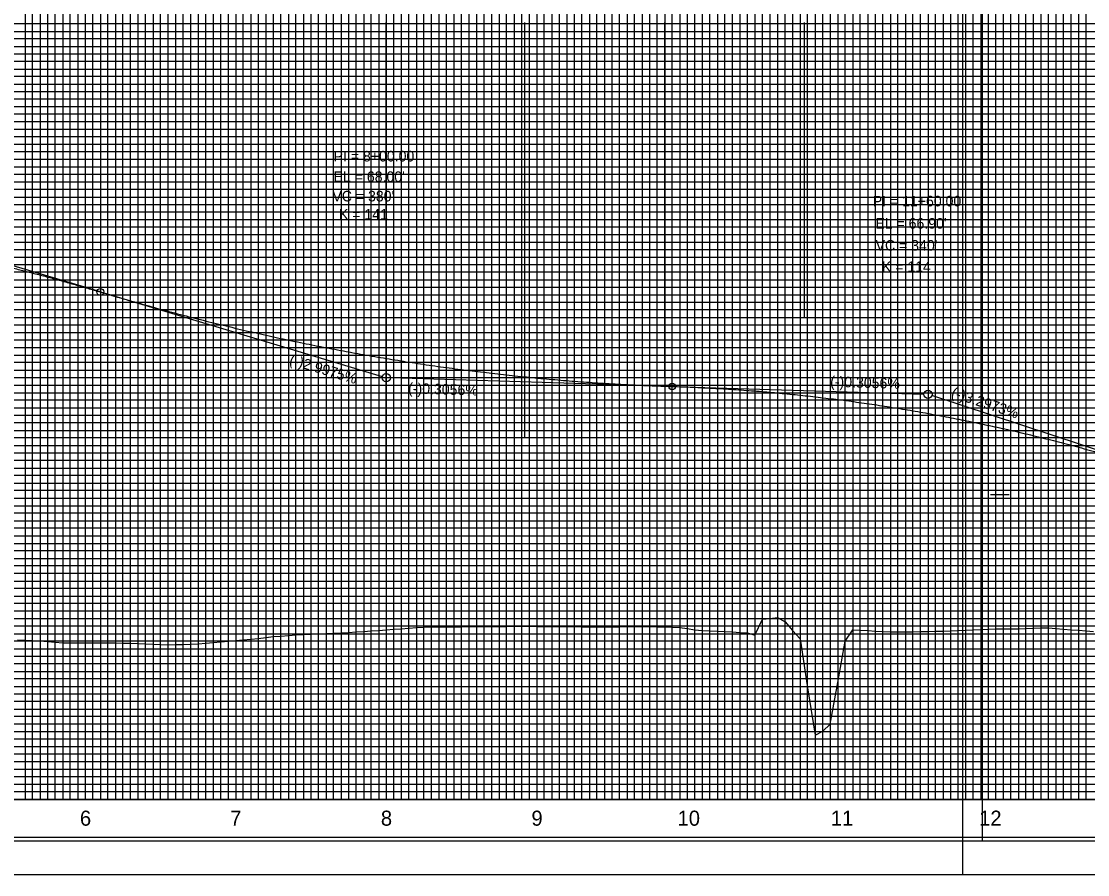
# Model space of a CAD drawing. Extents: x 2345490 to 2445302, y 465165 to 573888.
# Drawn here: x 2411453 to 2412161, y 502766 to 503333 of the extents above; entities that cross this region are included whole.
import ezdxf

# ---------------------------------------------------------------- set-up
doc = ezdxf.new("R2010")
doc.units = 0
for name, color, linetype in [('Old_Level_1', 7, 'Continuous'), ('Old_Level_18', 7, 'Continuous'), ('Old_Level_2', 7, 'Continuous'), ('Old_Level_41', 7, 'Continuous'), ('Old_Level_42', 7, 'Continuous'), ('Old_Level_43', 7, 'Continuous'), ('Old_Level_50', 7, 'Continuous'), ('Old_Level_51', 7, 'Continuous'), ('Old_Level_52', 7, 'Continuous'), ('Old_Level_63', 7, 'Continuous')]:
    doc.layers.add(name, color=color, linetype=linetype)

msp = doc.modelspace()

# ---------------------------------------------------------------- linework, layer by layer
at = {"layer": 'Old_Level_1'}
for points in [[(2411895.325, 502929.42025), (2411900.325, 502928.51975), (2411905.325, 502928.06175), (2411910.325, 502927.8235), (2411915.325, 502927.59575), (2411920.325, 502927.363), (2411925.325, 502927.125), (2411930.325, 502926.882), (2411935.325, 502926.634), (2411940.325, 502925.0755), (2411945.325, 502935.56225), (2411950.325, 502936.16175), (2411955.325, 502936.8355), (2411960.325, 502933.937), (2411965.325, 502928.20875), (2411970.325, 502922.47625), (2411975.325, 502889.98525), (2411980.325, 502858.67525), (2411985.325, 502861.2685), (2411990.325, 502865.85), (2411995.325, 502893.50925), (2412000.325, 502921.0655), (2412005.325, 502928.64375), (2412010.325, 502928.3405), (2412015.325, 502928.037), (2412020.325, 502927.73375), (2412025.325, 502927.43025), (2412030.325, 502927.18075), (2412035.325, 502927.1575), (2412040.325, 502927.13525), (2412045.325, 502927.228), (2412050.325, 502927.3485), (2412055.325, 502927.46975), (2412060.325, 502927.59125), (2412065.325, 502927.7135), (2412070.325, 502927.8935), (2412075.325, 502928.10225), (2412080.325, 502928.31675), (2412085.325, 502928.53075), (2412090.325, 502928.744), (2412095.325, 502928.95675), (2412100.325, 502929.16875), (2412105.325, 502929.224), (2412110.325, 502929.21625), (2412115.325, 502929.2085), (2412120.325, 502929.40675), (2412125.325, 502929.63475), (2412130.325, 502929.86325), (2412135.325, 502929.79875), (2412140.325, 502929.40475), (2412145.325, 502929.01325), (2412150.325, 502928.624), (2412155.325, 502928.23725), (2412160.325, 502927.86625), (2412165.325, 502927.51925)], [(2411450.325, 502921.841), (2411455.325, 502921.6385), (2411460.325, 502921.4365), (2411465.325, 502921.14575), (2411470.325, 502920.7305), (2411475.325, 502920.3155), (2411480.325, 502920.0265), (2411485.325, 502920.02675), (2411490.325, 502920.02575), (2411495.325, 502920.01025), (2411500.325, 502919.974), (2411505.325, 502919.9365), (2411510.325, 502919.8975), (2411515.325, 502919.8575), (2411520.325, 502919.816), (2411525.325, 502919.73875), (2411530.325, 502919.53175), (2411535.325, 502919.32475), (2411540.325, 502919.11775), (2411545.325, 502918.9105), (2411550.325, 502918.703), (2411555.325, 502918.7245), (2411560.325, 502918.89375), (2411565.325, 502919.0635), (2411570.325, 502919.25375), (2411575.325, 502919.71225), (2411580.325, 502920.17), (2411585.325, 502920.62725), (2411590.325, 502921.08375), (2411595.325, 502921.5395), (2411600.325, 502921.9775), (2411605.325, 502922.3685), (2411610.325, 502922.76875), (2411615.325, 502923.52525), (2411620.325, 502924.0925), (2411625.325, 502924.46075), (2411630.325, 502924.82975), (2411635.325, 502925.1995), (2411640.325, 502925.519), (2411645.325, 502925.70975), (2411650.325, 502925.901), (2411655.325, 502926.093), (2411660.325, 502926.28525), (2411665.325, 502926.478), (2411670.325, 502926.75725), (2411675.325, 502927.124), (2411680.325, 502927.4815), (2411685.325, 502927.83975), (2411690.325, 502928.19875), (2411695.325, 502928.55825), (2411700.325, 502928.91825), (2411705.325, 502929.279), (2411710.325, 502929.64), (2411715.325, 502930.00175), (2411720.325, 502930.364), (2411725.325, 502930.5915), (2411730.325, 502930.60275), (2411735.325, 502930.621), (2411740.325, 502930.64), (2411745.325, 502930.66), (2411750.325, 502930.681), (2411755.325, 502930.70925), (2411760.325, 502930.743), (2411765.325, 502930.77775), (2411770.325, 502930.81325), (2411775.325, 502930.84975), (2411780.325, 502930.93525), (2411785.325, 502930.9275), (2411790.325, 502930.8895), (2411795.325, 502930.852), (2411800.325, 502930.81475), (2411805.325, 502930.778), (2411810.325, 502930.7415), (2411815.325, 502930.7055), (2411820.325, 502930.67), (2411825.325, 502930.63475), (2411830.325, 502930.6), (2411835.325, 502930.56575), (2411840.325, 502930.5425), (2411845.325, 502930.5975), (2411850.325, 502930.6545), (2411855.325, 502930.7135), (2411860.325, 502930.77425), (2411865.325, 502930.837), (2411870.325, 502930.72125), (2411875.325, 502930.58425), (2411880.325, 502930.4495), (2411885.325, 502930.3165), (2411890.325, 502930.06375), (2411895.325, 502929.42025)]]:
    msp.add_lwpolyline(points, dxfattribs=at)
at = {"layer": 'Old_Level_18'}
msp.add_lwpolyline([(2412345.325, 503840.981), (2410845.325, 503840.981), (2410845.325, 502790.981), (2412345.325, 502790.981)], close=True, dxfattribs=at)
at = {"layer": 'Old_Level_2'}
for p, q in [((2411505.325, 503152.9335), (2411297.95925, 503215.0915)), ((2411505.325, 503152.9335), (2411692.691, 503096.77075)), ((2411885.325, 503090.1755), (2411698.07375, 503095.89725)), ((2411885.325, 503090.1755), (2412052.5765, 503085.065)), ((2412225.325, 503028.927), (2412057.93675, 503084.12))]:
    msp.add_line(p, q, dxfattribs=at)
for centre, radius in [((2411505.325, 503152.9335), 2.25), ((2411695.325, 503095.981), 2.75), ((2411885.325, 503090.1755), 2.25), ((2412055.325, 503084.981), 2.75)]:
    msp.add_circle(centre, radius, dxfattribs=at)
for points in [[(2411085.325, 503197.611), (2411093.725, 503198.3095), (2411102.125, 503198.94275), (2411110.525, 503199.51125), (2411118.925, 503200.0145), (2411127.325, 503200.453), (2411135.725, 503200.8265), (2411144.125, 503201.13475), (2411152.525, 503201.37825), (2411160.925, 503201.557), (2411169.325, 503201.6705), (2411177.725, 503201.719), (2411186.125, 503201.7025), (2411194.525, 503201.62125), (2411202.925, 503201.47475), (2411211.325, 503201.2635), (2411219.725, 503200.98725), (2411228.125, 503200.646), (2411236.525, 503200.23975), (2411244.925, 503199.7685), (2411253.325, 503199.23225), (2411261.725, 503198.63125), (2411270.125, 503197.965), (2411278.525, 503197.234), (2411286.925, 503196.43775), (2411295.325, 503195.57675), (2411303.725, 503194.65075), (2411312.125, 503193.65975), (2411320.525, 503192.60375), (2411328.925, 503191.48275), (2411337.325, 503190.29675), (2411345.725, 503189.046), (2411354.125, 503187.73), (2411362.525, 503186.34925), (2411370.925, 503184.90325), (2411379.325, 503183.3925), (2411387.725, 503181.81675), (2411396.125, 503180.176), (2411404.525, 503178.47025), (2411412.925, 503176.6995), (2411421.325, 503174.864), (2411429.725, 503172.96325), (2411438.125, 503170.99775), (2411446.525, 503168.967), (2411454.925, 503166.8715), (2411463.325, 503164.711), (2411471.725, 503162.4855), (2411480.125, 503160.195), (2411488.525, 503157.8395), (2411496.925, 503155.419), (2411505.325, 503152.9335)], [(2411505.325, 503152.9335), (2411512.925, 503150.676), (2411520.525, 503148.45925), (2411528.125, 503146.2835), (2411535.725, 503144.1485), (2411543.325, 503142.0545), (2411550.925, 503140.0015), (2411558.525, 503137.9895), (2411566.125, 503136.01825), (2411573.725, 503134.088), (2411581.325, 503132.1985), (2411588.925, 503130.35), (2411596.525, 503128.5425), (2411604.125, 503126.77575), (2411611.725, 503125.05025), (2411619.325, 503123.36525), (2411626.925, 503121.7215), (2411634.525, 503120.1185), (2411642.125, 503118.5565), (2411649.725, 503117.03525), (2411657.325, 503115.55525), (2411664.925, 503114.11575), (2411672.525, 503112.7175), (2411680.125, 503111.36), (2411687.725, 503110.0435), (2411695.325, 503108.76775), (2411702.925, 503107.53325), (2411710.525, 503106.33925), (2411718.125, 503105.1865), (2411725.725, 503104.0745), (2411733.325, 503103.0035), (2411740.925, 503101.9735), (2411748.525, 503100.98425), (2411756.125, 503100.036), (2411763.725, 503099.1285), (2411771.325, 503098.26225), (2411778.925, 503097.4365), (2411786.525, 503096.652), (2411794.125, 503095.90825), (2411801.725, 503095.2055), (2411809.325, 503094.54375), (2411816.925, 503093.92275), (2411824.525, 503093.34275), (2411832.125, 503092.8035), (2411839.725, 503092.3055), (2411847.325, 503091.84825), (2411854.925, 503091.43175), (2411862.525, 503091.05625), (2411870.125, 503090.72175), (2411877.725, 503090.42825), (2411885.325, 503090.1755)], [(2411885.325, 503090.1755), (2411892.125, 503089.9475), (2411898.925, 503089.67875), (2411905.725, 503089.36925), (2411912.525, 503089.019), (2411919.325, 503088.628), (2411926.125, 503088.1965), (2411932.925, 503087.72425), (2411939.725, 503087.21125), (2411946.525, 503086.65775), (2411953.325, 503086.0635), (2411960.125, 503085.4285), (2411966.925, 503084.75275), (2411973.725, 503084.03625), (2411980.525, 503083.27925), (2411987.325, 503082.4815), (2411994.125, 503081.643), (2412000.925, 503080.764), (2412007.725, 503079.84425), (2412014.525, 503078.88375), (2412021.325, 503077.8825), (2412028.125, 503076.8405), (2412034.925, 503075.758), (2412041.725, 503074.63475), (2412048.525, 503073.47075), (2412055.325, 503072.26625), (2412062.125, 503071.021), (2412068.925, 503069.735), (2412075.725, 503068.40825), (2412082.525, 503067.04075), (2412089.325, 503065.63275), (2412096.125, 503064.184), (2412102.925, 503062.6945), (2412109.725, 503061.1645), (2412116.525, 503059.59375), (2412123.325, 503057.98225), (2412130.125, 503056.33), (2412136.925, 503054.637), (2412143.725, 503052.9035), (2412150.525, 503051.12925), (2412157.325, 503049.31425), (2412164.125, 503047.45875), (2412170.925, 503045.56225), (2412177.725, 503043.62525), (2412184.525, 503041.64775), (2412191.325, 503039.62925), (2412198.125, 503037.57025), (2412204.925, 503035.4705), (2412211.725, 503033.33), (2412218.525, 503031.149), (2412225.325, 503028.927)]]:
    msp.add_spline(points, degree=3, dxfattribs=at)
at = {"layer": 'Old_Level_41'}
for p, q in [((2412096.825, 503018.481), (2412109.325, 503018.481)), ((2412345.325, 502815.981), (2410845.325, 502815.981))]:
    msp.add_line(p, q, dxfattribs=at)
for points in [[(2411470.325, 503840.981), (2411470.325, 502815.981), (2411520.325, 502815.981), (2411520.325, 503840.981)], [(2411495.325, 503840.981), (2411495.325, 502815.981), (2411545.325, 502815.981), (2411545.325, 503840.981)], [(2411570.325, 503840.981), (2411570.325, 502815.981), (2411620.325, 502815.981), (2411620.325, 503840.981)], [(2411595.325, 503840.981), (2411595.325, 502815.981), (2411645.325, 502815.981), (2411645.325, 503840.981)], [(2411670.325, 503840.981), (2411670.325, 502815.981), (2411720.325, 502815.981), (2411720.325, 503840.981)], [(2411695.325, 503840.981), (2411695.325, 502815.981), (2411745.325, 502815.981), (2411745.325, 503840.981)], [(2411770.325, 503840.981), (2411770.325, 502815.981), (2411820.325, 502815.981), (2411820.325, 503840.981)], [(2411795.325, 503840.981), (2411795.325, 502815.981), (2411845.325, 502815.981), (2411845.325, 503840.981)], [(2411870.325, 503840.981), (2411870.325, 502815.981), (2411920.325, 502815.981), (2411920.325, 503840.981)], [(2411895.325, 503840.981), (2411895.325, 502815.981), (2411945.325, 502815.981), (2411945.325, 503840.981)], [(2411970.325, 503840.981), (2411970.325, 502815.981), (2412020.325, 502815.981), (2412020.325, 503840.981)], [(2411995.325, 503840.981), (2411995.325, 502815.981), (2412045.325, 502815.981), (2412045.325, 503840.981)], [(2412070.325, 503840.981), (2412070.325, 502815.981), (2412120.325, 502815.981), (2412120.325, 503840.981)], [(2412095.325, 503840.981), (2412095.325, 502815.981), (2412145.325, 502815.981), (2412145.325, 503840.981)], [(2412345.325, 503340.981), (2410845.325, 503340.981), (2410845.325, 503290.981), (2412345.325, 503290.981)], [(2412345.325, 503240.981), (2410845.325, 503240.981), (2410845.325, 503190.981), (2412345.325, 503190.981)], [(2412345.325, 503165.981), (2410845.325, 503165.981), (2410845.325, 503215.981), (2412345.325, 503215.981)], [(2412345.325, 503140.981), (2410845.325, 503140.981), (2410845.325, 503090.981), (2412345.325, 503090.981)], [(2412345.325, 503065.981), (2410845.325, 503065.981), (2410845.325, 503115.981), (2412345.325, 503115.981)], [(2412345.325, 503040.981), (2410845.325, 503040.981), (2410845.325, 502990.981), (2412345.325, 502990.981)], [(2412345.325, 502940.981), (2410845.325, 502940.981), (2410845.325, 502890.981), (2412345.325, 502890.981)], [(2412345.325, 502865.981), (2410845.325, 502865.981), (2410845.325, 502915.981), (2412345.325, 502915.981)], [(2412345.325, 502840.981), (2410845.325, 502840.981)]]:
    msp.add_lwpolyline(points, dxfattribs=at)
at = {"layer": 'Old_Level_42'}
for points in [[(2412345.325, 503265.981), (2410845.325, 503265.981), (2410845.325, 503315.981), (2412345.325, 503315.981)], [(2412345.325, 502965.981), (2410845.325, 502965.981), (2410845.325, 503015.981), (2412345.325, 503015.981)]]:
    msp.add_lwpolyline(points, dxfattribs=at)
at = {"layer": 'Old_Level_43'}
for points in [[(2411455.325, 503840.981), (2411455.325, 502815.981), (2411455.325, 502815.981), (2411460.325, 502815.981), (2411460.325, 503840.981)], [(2411465.325, 503840.981), (2411465.325, 502815.981), (2411475.325, 502815.981), (2411475.325, 503840.981)], [(2411480.325, 503840.981), (2411480.325, 502815.981), (2411485.325, 502815.981), (2411485.325, 503840.981)], [(2411490.325, 503840.981), (2411490.325, 502815.981), (2411500.325, 502815.981), (2411500.325, 503840.981)], [(2411505.325, 503840.981), (2411505.325, 502815.981), (2411510.325, 502815.981), (2411510.325, 503840.981)], [(2411515.325, 503840.981), (2411515.325, 502815.981), (2411525.325, 502815.981), (2411525.325, 503840.981)], [(2411530.325, 503840.981), (2411530.325, 502815.981), (2411535.325, 502815.981), (2411535.325, 503840.981)], [(2411540.325, 503840.981), (2411540.325, 502815.981), (2411550.325, 502815.981), (2411550.325, 503840.981)], [(2411555.325, 503840.981), (2411555.325, 502815.981), (2411560.325, 502815.981), (2411560.325, 503840.981)], [(2411565.325, 503840.981), (2411565.325, 502815.981), (2411575.325, 502815.981), (2411575.325, 503840.981)], [(2411580.325, 503840.981), (2411580.325, 502815.981), (2411585.325, 502815.981), (2411585.325, 503840.981)], [(2411590.325, 503840.981), (2411590.325, 502815.981), (2411600.325, 502815.981), (2411600.325, 503840.981)], [(2411605.325, 503840.981), (2411605.325, 502815.981)], [(2411605.325, 502815.981), (2411610.325, 502815.981), (2411610.325, 503840.381)], [(2411615.325, 503840.381), (2411615.325, 502815.981), (2411625.325, 502815.981), (2411625.325, 503840.981)], [(2411630.325, 503840.981), (2411630.325, 502815.981), (2411635.325, 502815.981), (2411635.325, 503840.981)], [(2411640.325, 503840.981), (2411640.325, 502815.981), (2411650.325, 502815.981), (2411650.325, 503840.981)], [(2411655.325, 503840.981), (2411655.325, 502815.981), (2411660.325, 502815.981), (2411660.325, 503840.981)], [(2411665.325, 503840.981), (2411665.325, 502815.981), (2411675.325, 502815.981), (2411675.325, 503840.981)], [(2411680.325, 503840.981), (2411680.325, 502815.981), (2411685.325, 502815.981), (2411685.325, 503840.981)], [(2411690.325, 503840.981), (2411690.325, 502815.981), (2411700.325, 502815.981), (2411700.325, 503840.981)], [(2411705.325, 503840.981), (2411705.325, 502815.981), (2411710.325, 502815.981), (2411710.325, 503840.981)], [(2411715.325, 503840.981), (2411715.325, 502815.981), (2411725.325, 502815.981), (2411725.325, 503840.981)], [(2411730.325, 503840.981), (2411730.325, 502815.981), (2411735.325, 502815.981), (2411735.325, 503840.981)], [(2411740.325, 503840.981), (2411740.325, 502815.981), (2411750.325, 502815.981), (2411750.325, 503840.981)], [(2411755.325, 503840.981), (2411755.325, 502815.981), (2411760.325, 502815.981), (2411760.325, 503840.981)], [(2411765.325, 503840.981), (2411765.325, 502815.981), (2411775.325, 502815.981), (2411775.325, 503840.981)], [(2411780.325, 503840.981), (2411780.325, 502815.981), (2411785.325, 502815.981), (2411785.325, 503840.981)], [(2411790.325, 503840.981), (2411790.325, 502815.981), (2411800.325, 502815.981), (2411800.325, 503840.981)], [(2411805.325, 503840.981), (2411805.325, 502815.981), (2411810.325, 502815.981), (2411810.325, 503840.981)], [(2411815.325, 503840.981), (2411815.325, 502815.981), (2411825.325, 502815.981), (2411825.325, 503840.981)], [(2411830.325, 503840.981), (2411830.325, 502815.981), (2411835.325, 502815.981), (2411835.325, 503840.981)], [(2411840.325, 503840.981), (2411840.325, 502815.981), (2411850.325, 502815.981), (2411850.325, 503840.981)], [(2411855.325, 503840.981), (2411855.325, 502815.981), (2411860.325, 502815.981), (2411860.325, 503840.981)], [(2411865.325, 503840.981), (2411865.325, 502815.981), (2411875.325, 502815.981), (2411875.325, 503840.981)], [(2411880.325, 503840.981), (2411880.325, 502815.981), (2411885.325, 502815.981), (2411885.325, 503840.981)], [(2411890.325, 503840.981), (2411890.325, 502815.981), (2411900.325, 502815.981), (2411900.325, 503840.981)], [(2411905.325, 503840.981), (2411905.325, 502815.981), (2411910.325, 502815.981), (2411910.325, 503840.981)], [(2411915.325, 503840.981), (2411915.325, 502815.981)], [(2411915.325, 502815.981), (2411925.325, 502815.981), (2411925.325, 503840.981)], [(2411930.325, 503840.981), (2411930.325, 502815.981), (2411935.325, 502815.981), (2411935.325, 503840.981)], [(2411940.325, 503840.981), (2411940.325, 502815.981), (2411950.325, 502815.981), (2411950.325, 503840.981)], [(2411955.325, 503840.981), (2411955.325, 502815.981), (2411960.325, 502815.981), (2411960.325, 503840.981)], [(2411965.325, 503840.981), (2411965.325, 502815.981), (2411975.325, 502815.981), (2411975.325, 503840.981)], [(2411980.325, 503840.981), (2411980.325, 502815.981), (2411985.325, 502815.981), (2411985.325, 503840.981)], [(2411990.325, 503840.981), (2411990.325, 502815.981), (2412000.325, 502815.981), (2412000.325, 503840.981)], [(2412005.325, 503840.981), (2412005.325, 502815.981), (2412010.325, 502815.981), (2412010.325, 503840.981)], [(2412015.325, 503840.981), (2412015.325, 502815.981), (2412025.325, 502815.981), (2412025.325, 503840.981)], [(2412030.325, 503840.981), (2412030.325, 502815.981), (2412035.325, 502815.981), (2412035.325, 503840.981)], [(2412040.325, 503840.981), (2412040.325, 502815.981), (2412050.325, 502815.981), (2412050.325, 503840.981)], [(2412055.325, 503840.981), (2412055.325, 502815.981), (2412060.325, 502815.981), (2412060.325, 503840.981)], [(2412065.325, 503840.981), (2412065.325, 502815.981), (2412075.325, 502815.981), (2412075.325, 503840.981)], [(2412080.325, 503840.981), (2412080.325, 502815.981), (2412085.325, 502815.981), (2412085.325, 503840.981)], [(2412090.325, 503840.981), (2412090.325, 502815.981), (2412100.325, 502815.981), (2412100.325, 503840.981)], [(2412105.325, 503840.981), (2412105.325, 502815.981), (2412110.325, 502815.981), (2412110.325, 503840.981)], [(2412115.325, 503840.981), (2412115.325, 502815.981), (2412125.325, 502815.981), (2412125.325, 503840.981)], [(2412130.325, 503840.981), (2412130.325, 502815.981), (2412135.325, 502815.981), (2412135.325, 503840.981)], [(2412140.325, 503840.981), (2412140.325, 502815.981), (2412150.325, 502815.981), (2412150.325, 503703.431)], [(2412155.325, 503703.431), (2412155.325, 502815.981), (2412160.325, 502815.981), (2412160.325, 503703.431)], [(2412295.325, 503330.981), (2410895.325, 503330.981), (2410895.325, 503325.981), (2412295.325, 503325.981)], [(2412295.325, 503320.981), (2410895.325, 503320.981)], [(2410895.325, 503310.981), (2412295.325, 503310.981)], [(2412295.325, 503305.981), (2410895.325, 503305.981), (2410895.325, 503300.981), (2412295.325, 503300.981)], [(2412295.325, 503295.981), (2410895.325, 503295.981), (2410895.325, 503285.981), (2412295.325, 503285.981)], [(2412295.325, 503280.981), (2410895.325, 503280.981), (2410895.325, 503275.981), (2412295.325, 503275.981)], [(2412295.325, 503270.981), (2410895.325, 503270.981), (2410895.325, 503260.981), (2412295.325, 503260.981)], [(2412295.325, 503255.981), (2410895.325, 503255.981), (2410895.325, 503250.981), (2412295.325, 503250.981)], [(2412295.325, 503245.981), (2410895.325, 503245.981), (2410895.325, 503235.981), (2412295.325, 503235.981)], [(2412295.325, 503230.981), (2410895.325, 503230.981), (2410895.325, 503225.981), (2412295.325, 503225.981)], [(2412295.325, 503220.981), (2410895.325, 503220.981), (2410895.325, 503210.981), (2412295.325, 503210.981)], [(2412295.325, 503205.981), (2410895.325, 503205.981), (2410895.325, 503200.981), (2412295.325, 503200.981)], [(2412295.325, 503195.981), (2410895.325, 503195.981), (2410895.325, 503185.981), (2412295.325, 503185.981)], [(2412295.325, 503180.981), (2410895.325, 503180.981), (2410895.325, 503175.981), (2412295.325, 503175.981)], [(2412295.325, 503170.981), (2410895.325, 503170.981), (2410895.325, 503160.981), (2412295.325, 503160.981)], [(2412295.325, 503155.981), (2410895.325, 503155.981), (2410895.325, 503150.981), (2412295.325, 503150.981)], [(2412295.325, 503145.981), (2410895.325, 503145.981), (2410895.325, 503135.981), (2412295.325, 503135.981)], [(2412295.325, 503130.981), (2410895.325, 503130.981), (2410895.325, 503125.981), (2412295.325, 503125.981)], [(2412295.325, 503120.981), (2410895.325, 503120.981), (2410895.325, 503110.981), (2412295.325, 503110.981)], [(2412295.325, 503105.981), (2410895.325, 503105.981), (2410895.325, 503100.981), (2412295.325, 503100.981)], [(2412295.325, 503095.981), (2410895.325, 503095.981), (2410895.325, 503085.981), (2412295.325, 503085.981)], [(2412295.325, 503080.981), (2410895.325, 503080.981), (2410895.325, 503075.981), (2412295.325, 503075.981)], [(2412295.325, 503070.981), (2410895.325, 503070.981), (2410895.325, 503060.981), (2412295.325, 503060.981)], [(2412295.325, 503055.981), (2410895.325, 503055.981), (2410895.325, 503050.981), (2412295.325, 503050.981)], [(2412295.325, 503045.981), (2410895.325, 503045.981), (2410895.325, 503035.981), (2412295.325, 503035.981)], [(2412295.325, 503030.981), (2410895.325, 503030.981), (2410895.325, 503025.981), (2412295.325, 503025.981)], [(2412295.325, 503020.981), (2410895.325, 503020.981)], [(2410895.325, 503010.981), (2412295.325, 503010.981)], [(2412295.325, 503005.981), (2410895.325, 503005.981), (2410895.325, 503000.981), (2412295.325, 503000.981)], [(2412295.325, 502995.981), (2410895.325, 502995.981)], [(2410895.325, 502985.981), (2412295.325, 502985.981)], [(2412295.325, 502980.981), (2410895.325, 502980.981), (2410895.325, 502975.981), (2412295.325, 502975.981)], [(2412295.325, 502970.981), (2410895.325, 502970.981), (2410895.325, 502960.981), (2412295.325, 502960.981)], [(2412295.325, 502955.981), (2410895.325, 502955.981), (2410895.325, 502950.981), (2412295.325, 502950.981)], [(2412295.325, 502945.981), (2410895.325, 502945.981), (2410895.325, 502935.981), (2412295.325, 502935.981)], [(2412295.325, 502930.981), (2410895.325, 502930.981), (2410895.325, 502925.981), (2412295.325, 502925.981)], [(2412295.325, 502920.981), (2410895.325, 502920.981), (2410895.325, 502910.981), (2412295.325, 502910.981)], [(2412295.325, 502905.981), (2410895.325, 502905.981), (2410895.325, 502900.981), (2412295.325, 502900.981)], [(2412295.325, 502895.981), (2410895.325, 502895.981), (2410895.325, 502885.981), (2412295.325, 502885.981)], [(2412295.325, 502880.981), (2410895.325, 502880.981), (2410895.325, 502875.981), (2412295.325, 502875.981)], [(2412295.325, 502870.981), (2410895.325, 502870.981), (2410895.325, 502860.981), (2412295.325, 502860.981)], [(2412295.325, 502855.981), (2410895.325, 502855.981), (2410895.325, 502850.981), (2412295.325, 502850.981)], [(2412295.325, 502845.981), (2410895.325, 502845.981), (2410895.325, 502835.981), (2412295.325, 502835.981)], [(2412295.325, 502830.981), (2410895.325, 502830.981), (2410895.325, 502825.981), (2412295.325, 502825.981)], [(2412295.325, 502820.981), (2410895.325, 502820.981)]]:
    msp.add_lwpolyline(points, dxfattribs=at)
at = {"layer": 'Old_Level_50'}
msp.add_line((2412078.325, 502765.981), (2412078.325, 502765.981), dxfattribs=at)
for points in [[(2412357.825, 503843.531), (2410691.325, 503843.531), (2410691.325, 502788.431), (2412357.825, 502788.431)], [(2413757.825, 503843.531), (2412091.325, 503843.531), (2412091.325, 502788.431), (2413757.825, 502788.431)]]:
    msp.add_lwpolyline(points, close=True, dxfattribs=at)
at = {"layer": 'Old_Level_51'}
for points in [[(2412362.325, 503865.981), (2410678.325, 503865.981), (2410678.325, 502765.981), (2412362.325, 502765.981)], [(2413762.325, 503865.981), (2412078.325, 503865.981), (2412078.325, 502765.981), (2413762.325, 502765.981)]]:
    msp.add_lwpolyline(points, close=True, dxfattribs=at)
at = {"layer": 'Old_Level_52'}
msp.add_line((2412091.325, 502788.431), (2412091.325, 502788.431), dxfattribs=at)
at = {"layer": 'Old_Level_63'}
for p, q in [((2411695.325, 503025.981), (2411695.325, 503331.941)), ((2411787.325, 503055.981), (2411787.325, 503331.941)), ((2411880.325, 503095.981), (2411880.325, 503331.941)), ((2411973.325, 503135.981), (2411973.325, 503331.941)), ((2410895.325, 502815.981), (2412874.915, 502815.981))]:
    msp.add_line(p, q, dxfattribs=at)

# ---------------------------------------------------------------- texts
at = {"layer": 'Old_Level_1'}
for s, height, p in [('6', 10, (2411491.7645, 502798.481)), ('7', 10, (2411591.622, 502798.481)), ('8', 10, (2411691.748, 502798.481)), ('9', 10, (2411791.79025, 502798.481)), ('10', 10.000001, (2411888.9085, 502798.481)), ('11', 10.000001, (2411990.748, 502798.481)), ('12', 10.000001, (2412089.29625, 502798.481))]:
    msp.add_text(s, height=height, dxfattribs=at).set_placement(p)
at = {"layer": 'Old_Level_2'}
for s, height, p in [('PI = 8+00.00', 7.0000005, (2411660.325, 503239.59275)), ("EL = 68.00'", 7.0000005, (2411660.325, 503225.981)), ("VC = 380'", 7.000001, (2411659.52875, 503213.06)), ('PI = 11+60.00', 7.0000005, (2412018.58325, 503209.7545)), ('K = 141', 7.000001, (2411663.89325, 503201.00775)), ("EL = 66.90'", 7.0000005, (2412020.325, 503194.981)), ("VC = 340'", 7.000001, (2412020.48975, 503180.367)), ('K = 114', 7.000001, (2412024.67375, 503166.21075))]:
    msp.add_text(s, height=height, dxfattribs=at).set_placement(p)
for s, rotation, p in [('(-)2.9975%', 343.31389722, (2411630.3835, 503105.008)), ('(-)0.3056%', 358.24983889, (2411990.20825, 503089.97225)), ('(-)0.3056%', 358.24983889, (2411709.774, 503085.535)), ('(-)3.2973%', 341.751075, (2412070.17875, 503083.2425))]:
    msp.add_text(s, height=7.000001, rotation=rotation, dxfattribs=at).set_placement(p)

doc.saveas('drawing.dxf')
